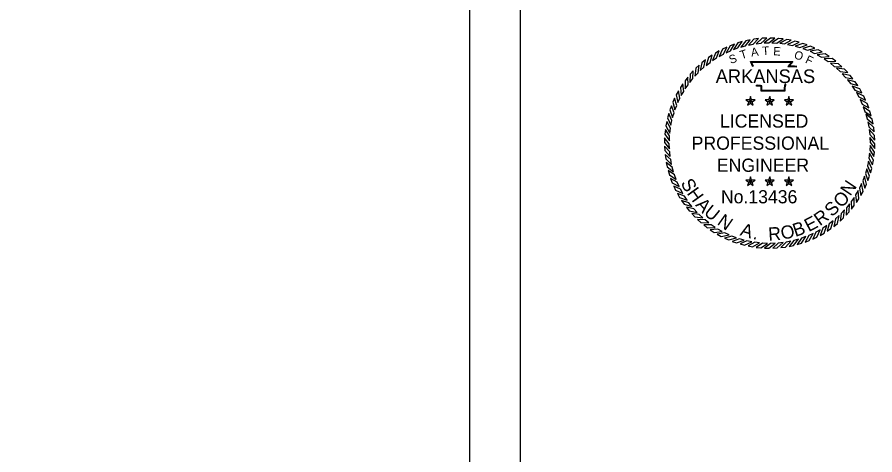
# Model space of a CAD drawing. Extents: x 1448008.9 to 1448047, y 2057056.5 to 2057079.8.
# Drawn here: x 1448037.23 to 1448046.96, y 2057068.14 to 2057073.11 of the extents above; entities that cross this region are included whole.
import ezdxf

# ---------------------------------------------------------------- set-up
doc = ezdxf.new("R2010")
doc.units = 0
doc.layers.add('1', color=7, linetype='Continuous')
doc.layers.add('G-ANNO-SYMB', color=7, linetype='Continuous')

msp = doc.modelspace()

# ---------------------------------------------------------------- linework, layer by layer
at = {"layer": '1'}
for q in [(1448042.3686, 2057079.2409), (1448042.3686, 2057077.9609)]:
    msp.add_line((1448042.3686, 2057058.3945), q, dxfattribs=at)
msp.add_lwpolyline([(1448042.9454, 2057079.8177), (1448008.9454, 2057079.8177), (1448008.9454, 2057057.8177), (1448042.9454, 2057057.8177)], close=True, dxfattribs=at)
at = {"layer": 'G-ANNO-SYMB'}
for points in [[(1448045.7365, 2057072.8708), (1448045.6852, 2057072.8682), (1448045.6178, 2057072.8065), (1448045.6729, 2057072.8126)], [(1448045.8302, 2057072.8698), (1448045.7789, 2057072.8713), (1448045.7068, 2057072.815), (1448045.7622, 2057072.8167)], [(1448045.3696, 2057072.8019), (1448045.3217, 2057072.7836), (1448045.2766, 2057072.704), (1448045.3271, 2057072.7269)], [(1448045.459, 2057072.8299), (1448045.4098, 2057072.8154), (1448045.3586, 2057072.7396), (1448045.4108, 2057072.7584)], [(1448045.5503, 2057072.8508), (1448045.5001, 2057072.8402), (1448045.4432, 2057072.7687), (1448045.4967, 2057072.7833)], [(1448045.643, 2057072.8645), (1448045.5921, 2057072.8579), (1448045.5298, 2057072.791), (1448045.5842, 2057072.8014)], [(1448045.9235, 2057072.8615), (1448045.8725, 2057072.8669), (1448045.7962, 2057072.8165), (1448045.8516, 2057072.8139)], [(1448046.0159, 2057072.8458), (1448045.9654, 2057072.8553), (1448045.8855, 2057072.811), (1448045.9405, 2057072.804)], [(1448046.1067, 2057072.823), (1448046.0572, 2057072.8364), (1448045.974, 2057072.7984), (1448046.0283, 2057072.7872)], [(1448046.1955, 2057072.7931), (1448046.1472, 2057072.8103), (1448046.0613, 2057072.779), (1448046.1145, 2057072.7636)], [(1448046.2817, 2057072.7563), (1448046.2349, 2057072.7773), (1448046.1467, 2057072.7528), (1448046.1986, 2057072.7333)], [(1448045.1183, 2057072.6772), (1448045.076, 2057072.6483), (1448045.0508, 2057072.5604), (1448045.0946, 2057072.5944)], [(1448045.1987, 2057072.7253), (1448045.1542, 2057072.6998), (1448045.1222, 2057072.6141), (1448045.1685, 2057072.6446)], [(1448045.2827, 2057072.767), (1448045.2363, 2057072.745), (1448045.1977, 2057072.6621), (1448045.2462, 2057072.6888)], [(1448046.3647, 2057072.7129), (1448046.3197, 2057072.7375), (1448046.2299, 2057072.72), (1448046.2801, 2057072.6964)], [(1448046.4441, 2057072.6631), (1448046.4011, 2057072.6911), (1448046.3102, 2057072.6808), (1448046.3584, 2057072.6533)], [(1448045.042, 2057072.623), (1448045.002, 2057072.5908), (1448044.9838, 2057072.5012), (1448045.0248, 2057072.5385)], [(1448046.5193, 2057072.6072), (1448046.4786, 2057072.6385), (1448046.3872, 2057072.6353), (1448046.4331, 2057072.6042)], [(1448046.5899, 2057072.5456), (1448046.5518, 2057072.58), (1448046.4604, 2057072.584), (1448046.5037, 2057072.5494)], [(1448044.9031, 2057072.4974), (1448044.8687, 2057072.4593), (1448044.8647, 2057072.368), (1448044.8994, 2057072.4112)], [(1448044.9701, 2057072.5629), (1448044.9328, 2057072.5277), (1448044.9216, 2057072.4369), (1448044.9596, 2057072.4773)], [(1448046.6554, 2057072.4786), (1448046.6202, 2057072.5159), (1448046.5294, 2057072.5271), (1448046.5698, 2057072.4892)], [(1448044.8415, 2057072.4268), (1448044.8102, 2057072.3861), (1448044.8134, 2057072.2947), (1448044.8445, 2057072.3406)], [(1448046.7155, 2057072.4068), (1448046.6833, 2057072.4467), (1448046.5937, 2057072.4649), (1448046.631, 2057072.4239)], [(1448046.7697, 2057072.3304), (1448046.7408, 2057072.3727), (1448046.6528, 2057072.3979), (1448046.6868, 2057072.3541)], [(1448044.7856, 2057072.3516), (1448044.7576, 2057072.3086), (1448044.7679, 2057072.2177), (1448044.7954, 2057072.2659)], [(1448046.8178, 2057072.25), (1448046.7923, 2057072.2945), (1448046.7066, 2057072.3265), (1448046.7371, 2057072.2802)], [(1448044.6924, 2057072.1892), (1448044.6714, 2057072.1424), (1448044.6959, 2057072.0543), (1448044.7155, 2057072.1061)], [(1448044.7358, 2057072.2722), (1448044.7112, 2057072.2272), (1448044.7287, 2057072.1374), (1448044.7523, 2057072.1876)], [(1448045.5524, 2057072.1532), (1448045.5647, 2057072.1701), (1448045.5524, 2057072.2078), (1448045.5402, 2057072.1701)], [(1448045.7706, 2057072.1532), (1448045.7828, 2057072.1701), (1448045.7706, 2057072.2078), (1448045.7584, 2057072.1701)], [(1448045.9888, 2057072.1532), (1448046.001, 2057072.1701), (1448045.9888, 2057072.2078), (1448045.9765, 2057072.1701)], [(1448046.8595, 2057072.166), (1448046.8375, 2057072.2124), (1448046.7546, 2057072.2511), (1448046.7813, 2057072.2025)], [(1448044.6556, 2057072.103), (1448044.6384, 2057072.0547), (1448044.6697, 2057071.9688), (1448044.6851, 2057072.022)], [(1448045.5524, 2057072.1532), (1448045.5402, 2057072.1701), (1448045.5005, 2057072.1701), (1448045.5326, 2057072.1468)], [(1448045.5524, 2057072.1532), (1448045.5326, 2057072.1468), (1448045.5204, 2057072.1091), (1448045.5524, 2057072.1324)], [(1448045.5524, 2057072.1532), (1448045.5722, 2057072.1468), (1448045.6043, 2057072.1701), (1448045.5647, 2057072.1701)], [(1448045.5524, 2057072.1532), (1448045.5524, 2057072.1324), (1448045.5845, 2057072.1091), (1448045.5722, 2057072.1468)], [(1448045.7706, 2057072.1532), (1448045.7584, 2057072.1701), (1448045.7187, 2057072.1701), (1448045.7508, 2057072.1468)], [(1448045.7706, 2057072.1532), (1448045.7508, 2057072.1468), (1448045.7385, 2057072.1091), (1448045.7706, 2057072.1324)], [(1448045.7706, 2057072.1532), (1448045.7904, 2057072.1468), (1448045.8225, 2057072.1701), (1448045.7828, 2057072.1701)], [(1448045.7706, 2057072.1532), (1448045.7706, 2057072.1324), (1448045.8027, 2057072.1091), (1448045.7904, 2057072.1468)], [(1448045.9888, 2057072.1532), (1448045.9765, 2057072.1701), (1448045.9369, 2057072.1701), (1448045.969, 2057072.1468)], [(1448045.9888, 2057072.1532), (1448045.969, 2057072.1468), (1448045.9567, 2057072.1091), (1448045.9888, 2057072.1324)], [(1448045.9888, 2057072.1532), (1448046.0086, 2057072.1468), (1448046.0407, 2057072.1701), (1448046.001, 2057072.1701)], [(1448045.9888, 2057072.1532), (1448045.9888, 2057072.1324), (1448046.0208, 2057072.1091), (1448046.0086, 2057072.1468)], [(1448046.8944, 2057072.0791), (1448046.8761, 2057072.1271), (1448046.7965, 2057072.1721), (1448046.8193, 2057072.1216)], [(1448044.6257, 2057072.0142), (1448044.6123, 2057071.9647), (1448044.6503, 2057071.8815), (1448044.6615, 2057071.9358)], [(1448046.9224, 2057071.9897), (1448046.9079, 2057072.0389), (1448046.8321, 2057072.0901), (1448046.8509, 2057072.0379)], [(1448046.9433, 2057071.8984), (1448046.9327, 2057071.9486), (1448046.8612, 2057072.0055), (1448046.8758, 2057071.9521)], [(1448044.6029, 2057071.9234), (1448044.5934, 2057071.873), (1448044.6378, 2057071.793), (1448044.6447, 2057071.848)], [(1448046.9569, 2057071.8057), (1448046.9504, 2057071.8566), (1448046.8835, 2057071.9189), (1448046.8939, 2057071.8645)], [(1448044.5872, 2057071.831), (1448044.5818, 2057071.78), (1448044.6322, 2057071.7037), (1448044.6348, 2057071.7591)], [(1448046.9633, 2057071.7122), (1448046.9607, 2057071.7635), (1448046.8989, 2057071.8309), (1448046.905, 2057071.7758)], [(1448044.5789, 2057071.7377), (1448044.5774, 2057071.6864), (1448044.6337, 2057071.6143), (1448044.632, 2057071.6697)], [(1448046.9623, 2057071.6185), (1448046.9638, 2057071.6698), (1448046.9075, 2057071.7419), (1448046.9092, 2057071.6865)], [(1448044.5779, 2057071.644), (1448044.5805, 2057071.5928), (1448044.6423, 2057071.5253), (1448044.6362, 2057071.5804)], [(1448046.9539, 2057071.5252), (1448046.9594, 2057071.5762), (1448046.909, 2057071.6525), (1448046.9064, 2057071.5971)], [(1448044.5842, 2057071.5505), (1448044.5908, 2057071.4997), (1448044.6577, 2057071.4373), (1448044.6473, 2057071.4917)], [(1448046.9383, 2057071.4328), (1448046.9478, 2057071.4833), (1448046.9034, 2057071.5633), (1448046.8965, 2057071.5083)], [(1448044.5979, 2057071.4579), (1448044.6085, 2057071.4076), (1448044.68, 2057071.3507), (1448044.6654, 2057071.4042)], [(1448046.9155, 2057071.342), (1448046.9289, 2057071.3915), (1448046.8909, 2057071.4747), (1448046.8797, 2057071.4204)], [(1448044.6188, 2057071.3665), (1448044.6333, 2057071.3173), (1448044.7091, 2057071.2662), (1448044.6903, 2057071.3183)], [(1448046.8856, 2057071.2532), (1448046.9028, 2057071.3015), (1448046.8715, 2057071.3875), (1448046.8561, 2057071.3342)], [(1448044.6468, 2057071.2771), (1448044.6651, 2057071.2292), (1448044.7447, 2057071.1841), (1448044.7219, 2057071.2347)], [(1448045.5524, 2057071.2396), (1448045.5402, 2057071.2565), (1448045.5005, 2057071.2565), (1448045.5326, 2057071.2332)], [(1448045.5524, 2057071.2396), (1448045.5326, 2057071.2332), (1448045.5204, 2057071.1955), (1448045.5524, 2057071.2188)], [(1448045.5524, 2057071.2396), (1448045.5647, 2057071.2565), (1448045.5524, 2057071.2942), (1448045.5402, 2057071.2565)], [(1448045.5524, 2057071.2396), (1448045.5722, 2057071.2332), (1448045.6043, 2057071.2565), (1448045.5647, 2057071.2565)], [(1448045.5524, 2057071.2396), (1448045.5524, 2057071.2188), (1448045.5845, 2057071.1955), (1448045.5722, 2057071.2332)], [(1448045.7706, 2057071.2396), (1448045.7584, 2057071.2565), (1448045.7187, 2057071.2565), (1448045.7508, 2057071.2332)], [(1448045.7706, 2057071.2396), (1448045.7508, 2057071.2332), (1448045.7385, 2057071.1955), (1448045.7706, 2057071.2188)], [(1448045.7706, 2057071.2396), (1448045.7828, 2057071.2565), (1448045.7706, 2057071.2942), (1448045.7584, 2057071.2565)], [(1448045.7706, 2057071.2396), (1448045.7904, 2057071.2332), (1448045.8225, 2057071.2565), (1448045.7828, 2057071.2565)], [(1448045.7706, 2057071.2396), (1448045.7706, 2057071.2188), (1448045.8027, 2057071.1955), (1448045.7904, 2057071.2332)], [(1448045.9888, 2057071.2396), (1448045.9765, 2057071.2565), (1448045.9369, 2057071.2565), (1448045.969, 2057071.2332)], [(1448045.9888, 2057071.2396), (1448045.969, 2057071.2332), (1448045.9567, 2057071.1955), (1448045.9888, 2057071.2188)], [(1448045.9888, 2057071.2396), (1448046.001, 2057071.2565), (1448045.9888, 2057071.2942), (1448045.9765, 2057071.2565)], [(1448045.9888, 2057071.2396), (1448046.0086, 2057071.2332), (1448046.0407, 2057071.2565), (1448046.001, 2057071.2565)], [(1448045.9888, 2057071.2396), (1448045.9888, 2057071.2188), (1448046.0208, 2057071.1955), (1448046.0086, 2057071.2332)], [(1448046.8054, 2057071.084), (1448046.8299, 2057071.129), (1448046.8125, 2057071.2188), (1448046.7889, 2057071.1687)], [(1448046.8488, 2057071.167), (1448046.8698, 2057071.2139), (1448046.8453, 2057071.302), (1448046.8257, 2057071.2501)], [(1448044.6817, 2057071.1902), (1448044.7037, 2057071.1438), (1448044.7866, 2057071.1052), (1448044.7599, 2057071.1537)], [(1448046.7556, 2057071.0047), (1448046.7836, 2057071.0476), (1448046.7732, 2057071.1385), (1448046.7458, 2057071.0903)], [(1448044.7234, 2057071.1063), (1448044.7489, 2057071.0618), (1448044.8346, 2057071.0297), (1448044.8041, 2057071.0761)], [(1448044.7715, 2057071.0259), (1448044.8004, 2057070.9835), (1448044.8883, 2057070.9583), (1448044.8544, 2057071.0021)], [(1448046.6997, 2057070.9295), (1448046.731, 2057070.9701), (1448046.7278, 2057071.0615), (1448046.6967, 2057071.0156)], [(1448044.8257, 2057070.9495), (1448044.8579, 2057070.9095), (1448044.9475, 2057070.8913), (1448044.9102, 2057070.9323)], [(1448046.6381, 2057070.8589), (1448046.6725, 2057070.8969), (1448046.6765, 2057070.9883), (1448046.6418, 2057070.945)], [(1448044.8858, 2057070.8776), (1448044.921, 2057070.8403), (1448045.0118, 2057070.8291), (1448044.9714, 2057070.8671)], [(1448046.4992, 2057070.7332), (1448046.5392, 2057070.7654), (1448046.5574, 2057070.8551), (1448046.5164, 2057070.8177)], [(1448046.5711, 2057070.7933), (1448046.6084, 2057070.8286), (1448046.6196, 2057070.9193), (1448046.5816, 2057070.8789)], [(1448044.9513, 2057070.8106), (1448044.9894, 2057070.7762), (1448045.0808, 2057070.7722), (1448045.0375, 2057070.8069)], [(1448045.0219, 2057070.749), (1448045.0626, 2057070.7177), (1448045.154, 2057070.7209), (1448045.1081, 2057070.752)], [(1448046.3425, 2057070.6309), (1448046.387, 2057070.6564), (1448046.419, 2057070.7421), (1448046.3727, 2057070.7117)], [(1448046.4229, 2057070.679), (1448046.4652, 2057070.708), (1448046.4904, 2057070.7959), (1448046.4466, 2057070.7619)], [(1448045.0971, 2057070.6932), (1448045.1401, 2057070.6651), (1448045.231, 2057070.6755), (1448045.1828, 2057070.7029)], [(1448045.1765, 2057070.6434), (1448045.2215, 2057070.6188), (1448045.3113, 2057070.6362), (1448045.2611, 2057070.6598)], [(1448046.1716, 2057070.5543), (1448046.2195, 2057070.5726), (1448046.2646, 2057070.6522), (1448046.2141, 2057070.6294)], [(1448046.2585, 2057070.5893), (1448046.3049, 2057070.6112), (1448046.3435, 2057070.6941), (1448046.295, 2057070.6674)], [(1448045.2595, 2057070.5999), (1448045.3063, 2057070.579), (1448045.3945, 2057070.6034), (1448045.3426, 2057070.623)], [(1448045.3457, 2057070.5632), (1448045.394, 2057070.5459), (1448045.4799, 2057070.5772), (1448045.4267, 2057070.5926)], [(1448045.4345, 2057070.5333), (1448045.484, 2057070.5199), (1448045.5672, 2057070.5578), (1448045.5129, 2057070.569)], [(1448045.5253, 2057070.5104), (1448045.5758, 2057070.5009), (1448045.6557, 2057070.5453), (1448045.6007, 2057070.5522)], [(1448045.6177, 2057070.4948), (1448045.6687, 2057070.4893), (1448045.745, 2057070.5398), (1448045.6896, 2057070.5424)], [(1448045.711, 2057070.4864), (1448045.7623, 2057070.485), (1448045.8344, 2057070.5413), (1448045.779, 2057070.5395)], [(1448045.8047, 2057070.4854), (1448045.8559, 2057070.488), (1448045.9234, 2057070.5498), (1448045.8683, 2057070.5437)], [(1448045.8982, 2057070.4918), (1448045.9491, 2057070.4983), (1448046.0114, 2057070.5652), (1448045.957, 2057070.5548)], [(1448045.9909, 2057070.5054), (1448046.0411, 2057070.516), (1448046.098, 2057070.5876), (1448046.0445, 2057070.5729)], [(1448046.0822, 2057070.5263), (1448046.1314, 2057070.5408), (1448046.1826, 2057070.6166), (1448046.1304, 2057070.5978)]]:
    msp.add_lwpolyline(points, close=True, dxfattribs=at)
for points in [[(1448045.5794, 2057072.5441), (1448045.5516, 2057072.6044), (1448046.0329, 2057072.6046), (1448045.9927, 2057072.5541), (1448046.0254, 2057072.5545), (1448046.0527, 2057072.5549), (1448046.08, 2057072.5519)], [(1448045.5864, 2057072.5473), (1448045.5635, 2057072.5967), (1448046.0171, 2057072.597), (1448045.9767, 2057072.5463), (1448046.0255, 2057072.5469), (1448046.0523, 2057072.5473), (1448046.0792, 2057072.5443)], [(1448045.9571, 2057072.3424), (1448045.9489, 2057072.3357), (1448045.9461, 2057072.3258), (1448045.9434, 2057072.3008), (1448045.9434, 2057072.2676), (1448045.6747, 2057072.2676), (1448045.6747, 2057072.3125), (1448045.6747, 2057072.3224), (1448045.6638, 2057072.3258), (1448045.6256, 2057072.3258), (1448045.6188, 2057072.3361)], [(1448045.9522, 2057072.3483), (1448045.9421, 2057072.3401), (1448045.9386, 2057072.3272), (1448045.9358, 2057072.3012), (1448045.9358, 2057072.2752), (1448045.6824, 2057072.2752), (1448045.6824, 2057072.3125), (1448045.6824, 2057072.3281), (1448045.665, 2057072.3334), (1448045.6297, 2057072.3334), (1448045.6252, 2057072.3403)]]:
    msp.add_lwpolyline(points, dxfattribs=at)

# ---------------------------------------------------------------- texts
for s, height, rotation, p in [('T', 0.0949, 1.47887, (1448045.6874, 2057072.6789)), ('S', 0.0949, 19.77256, (1448045.3288, 2057072.5757)), ('T', 0.0949, 16.90148, (1448045.4495, 2057072.6299)), ('A', 0.0949, 8.67877, (1448045.5648, 2057072.66)), ('E', 0.0949, 356.67203, (1448045.8089, 2057072.676)), ('O', 0.0949, 341.2218, (1448046.0394, 2057072.6434)), ('F', 0.0949, 335.36282, (1448046.1673, 2057072.5934)), ('ARKANSAS', 0.15494, 360, (1448045.1582, 2057072.3597)), ('LICENSED', 0.15, 360, (1448045.2063, 2057071.854)), ('PROFESSIONAL', 0.150001, 360, (1448044.8849, 2057071.6031)), ('ENGINEER', 0.15, 360, (1448045.1706, 2057071.3523)), ('S', 0.15, 298.16364, (1448044.757, 2057071.2262)), ('N', 0.15, 56.10067, (1448046.6854, 2057071.0694)), ('H', 0.15, 305.61905, (1448044.8254, 2057071.1086)), ('No.13436', 0.14941, 360, (1448045.2179, 2057070.9947)), ('O', 0.15, 44.77573, (1448046.5812, 2057070.9344)), ('A', 0.15, 313.44722, (1448044.9206, 2057070.9717)), ('U', 0.15, 320.90262, (1448045.0141, 2057070.8739)), ('S', 0.15, 43.48784, (1448046.4782, 2057070.8349)), ('N', 0.15, 324.93262, (1448045.1653, 2057070.7622)), ('E', 0.15, 27.83149, (1448046.2135, 2057070.6665)), ('R', 0.15, 35.65967, (1448046.3402, 2057070.7329)), ('A', 0.15, 343.09908, (1448045.4268, 2057070.6335)), ('O', 0.15, 11.42961, (1448045.9116, 2057070.5805)), ('B', 0.15, 18.88501, (1448046.062, 2057070.6123)), ('R', 0.15, 3.22866, (1448045.7581, 2057070.5708)), ('.', 0.15, 351.30002, (1448045.5742, 2057070.5898))]:
    msp.add_text(s, height=height, rotation=rotation, dxfattribs=at).set_placement(p)

doc.saveas('drawing.dxf')
